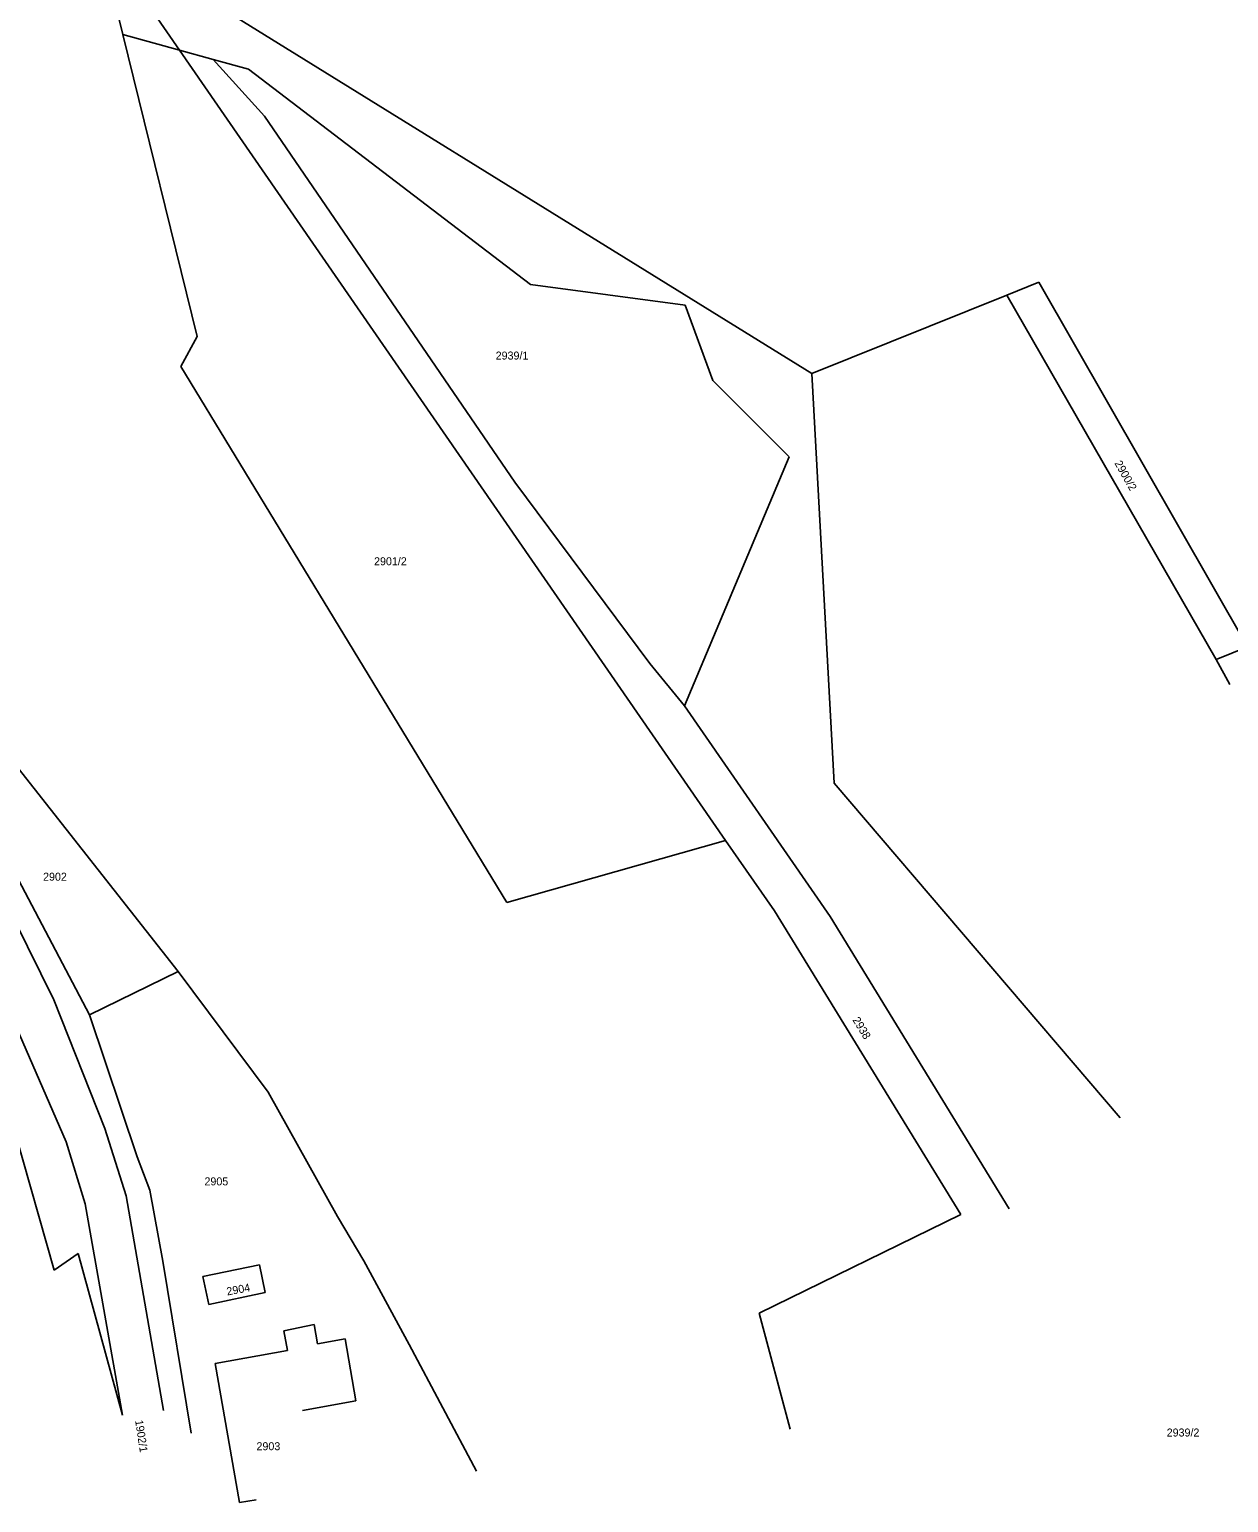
# Model space of a CAD drawing. Extents: x -722132 to -721608, y -1046877 to -1046449.
# Drawn here: x -721938.8 to -721811.3, y -1046877.2 to -1046720.6 of the extents above; entities that cross this region are included whole.
import ezdxf

# ---------------------------------------------------------------- set-up
doc = ezdxf.new("R2010")
doc.units = 0
for name, color, linetype in [('Vrstva 1', 7, 'Continuous'), ('Vrstva 16', 7, 'Continuous'), ('Vrstva 18', 7, 'Continuous'), ('Vrstva 19', 7, 'Continuous'), ('Vrstva 4', 7, 'Continuous'), ('Vrstva 6', 7, 'Continuous')]:
    doc.layers.add(name, color=color, linetype=linetype)

msp = doc.modelspace()

# ---------------------------------------------------------------- linework, layer by layer
at = {"layer": 'Vrstva 1'}
for points in [[(-721931.6, -1046710.14), (-721855.63, -1046757.17)], [(-721855.63, -1046757.17), (-721834.89, -1046748.83)], [(-721834.89, -1046748.83), (-721831.5, -1046747.47)], [(-721834.89, -1046748.83), (-721812.66, -1046787.58)], [(-721831.5, -1046747.47), (-721809.33, -1046786.25)], [(-721958.77, -1046775.35), (-721932.42, -1046825.36)], [(-721958.77, -1046775.35), (-721923, -1046820.76)], [(-721812.66, -1046787.58), (-721809.33, -1046786.25)], [(-721812.66, -1046787.58), (-721811.2, -1046790.23)], [(-721932.42, -1046825.36), (-721923, -1046820.76)], [(-721923, -1046820.76), (-721913.43, -1046833.59)], [(-721932.42, -1046825.36), (-721927.36, -1046840.47)], [(-721913.43, -1046833.59), (-721906.06, -1046846.81)], [(-721940.32, -1046837.92), (-721936.19, -1046852.5)], [(-721927.36, -1046840.47), (-721926.03, -1046843.99)], [(-721926.03, -1046843.99), (-721924.64, -1046851.55)], [(-721906.06, -1046846.81), (-721903.28, -1046851.52)], [(-721924.64, -1046851.55), (-721921.61, -1046869.83)], [(-721920.37, -1046853.17), (-721914.37, -1046851.94)], [(-721914.37, -1046851.94), (-721913.75, -1046854.89)], [(-721903.28, -1046851.52), (-721898.46, -1046860.42)], [(-721920.37, -1046853.17), (-721919.74, -1046856.14)], [(-721919.74, -1046856.14), (-721913.75, -1046854.89)], [(-721911.77, -1046858.94), (-721908.56, -1046858.29)], [(-721908.56, -1046858.29), (-721908.2, -1046860.32)], [(-721911.77, -1046858.94), (-721911.39, -1046861.04)], [(-721908.2, -1046860.32), (-721905.24, -1046859.81)], [(-721905.24, -1046859.81), (-721904.12, -1046866.4)], [(-721919.06, -1046862.42), (-721911.39, -1046861.04)], [(-721898.46, -1046860.42), (-721891.29, -1046873.89)], [(-721919.06, -1046862.42), (-721916.48, -1046877.21)], [(-721909.78, -1046867.41), (-721904.12, -1046866.4)], [(-721916.48, -1046877.21), (-721914.7, -1046876.93)]]:
    msp.add_lwpolyline(points, dxfattribs=at)
at = {"layer": 'Vrstva 4'}
for points in [[(-721957.14, -1046781.47), (-721936.21, -1046823.76)], [(-721936.21, -1046823.76), (-721930.82, -1046837.46)], [(-721940.59, -1046825.83), (-721934.9, -1046838.85)], [(-721930.82, -1046837.46), (-721928.53, -1046844.61)], [(-721934.9, -1046838.85), (-721932.9, -1046845.45)], [(-721932.9, -1046845.45), (-721928.91, -1046867.92)], [(-721928.53, -1046844.61), (-721924.58, -1046867.42)]]:
    msp.add_lwpolyline(points, dxfattribs=at)
at = {"layer": 'Vrstva 6'}
for points in [[(-721931.6, -1046710.14), (-721928.89, -1046721.13)], [(-721931.6, -1046710.14), (-721922.86, -1046722.8)], [(-721928.89, -1046721.13), (-721920.99, -1046753.24)], [(-721928.89, -1046721.13), (-721922.86, -1046722.8)], [(-721922.86, -1046722.8), (-721864.81, -1046806.84)], [(-721922.86, -1046722.8), (-721919.27, -1046723.79)], [(-721919.27, -1046723.79), (-721915.53, -1046724.82)], [(-721919.27, -1046723.79), (-721913.83, -1046729.81)], [(-721915.53, -1046724.82), (-721885.54, -1046747.7)], [(-721913.83, -1046729.81), (-721887.22, -1046768.74)], [(-721885.54, -1046747.7), (-721869.09, -1046749.9)], [(-721869.09, -1046749.9), (-721866.16, -1046757.93)], [(-721922.73, -1046756.44), (-721920.99, -1046753.24)], [(-721922.73, -1046756.44), (-721888.06, -1046813.43)], [(-721866.16, -1046757.93), (-721858.04, -1046766.02)], [(-721855.63, -1046757.17), (-721853.26, -1046800.73)], [(-721869.19, -1046792.49), (-721858.04, -1046766.02)], [(-721887.22, -1046768.74), (-721872.85, -1046787.99)], [(-721872.85, -1046787.99), (-721869.19, -1046792.49)], [(-721869.19, -1046792.49), (-721853.68, -1046814.9)], [(-721853.26, -1046800.73), (-721822.87, -1046836.32)], [(-721888.06, -1046813.43), (-721864.81, -1046806.84)], [(-721864.81, -1046806.84), (-721859.61, -1046814.29)], [(-721859.61, -1046814.29), (-721839.8, -1046846.59)], [(-721853.68, -1046814.9), (-721834.67, -1046845.98)], [(-721861.23, -1046857.06), (-721839.8, -1046846.59)], [(-721936.19, -1046852.5), (-721933.64, -1046850.72)], [(-721933.64, -1046850.72), (-721928.91, -1046867.92)], [(-721861.23, -1046857.06), (-721857.94, -1046869.41)]]:
    msp.add_lwpolyline(points, dxfattribs=at)

# ---------------------------------------------------------------- texts
at = {"layer": 'Vrstva 16'}
msp.add_text('1902/1', height=0.85, rotation=278.7038, dxfattribs=at).set_placement((-721927.59, -1046868.49))
at = {"layer": 'Vrstva 18'}
for s, p in [('2939/1', (-721889.25, -1046755.69)), ('2901/2', (-721902.18, -1046777.56)), ('2902', (-721937.37, -1046811.1)), ('2905', (-721920.21, -1046843.49)), ('2939/2', (-721817.91, -1046870.19))]:
    msp.add_text(s, height=0.85, dxfattribs=at).set_placement(p)
for s, rotation, p in [('2900/2', 299.5582, (-721823.49, -1046766.71)), ('2938', 301.1444, (-721851.35, -1046825.89))]:
    msp.add_text(s, height=0.85, rotation=rotation, dxfattribs=at).set_placement(p)
at = {"layer": 'Vrstva 19'}
msp.add_text('2904', height=0.85, rotation=10.5537, dxfattribs=at).set_placement((-721917.78, -1046855.2))
msp.add_text('2903', height=0.85, dxfattribs=at).set_placement((-721914.68, -1046871.65))

doc.saveas('drawing.dxf')
